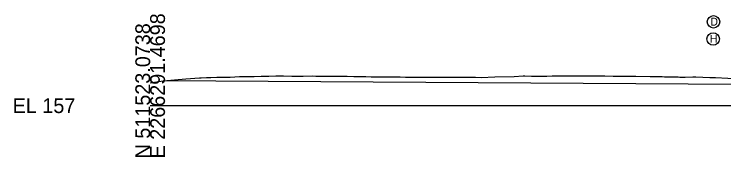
# Model space of a CAD drawing. Extents: x -516 to 303, y -10 to 5017.
# Drawn here: x -25.7 to 108.4, y 2990.3 to 3017.3 of the extents above; entities that cross this region are included whole.
import ezdxf

# ---------------------------------------------------------------- set-up
doc = ezdxf.new("R2010")
doc.units = 0
for name, color, linetype in [('Default', 7, 'Continuous'), ('Exist Cross Section Cell', 7, 'Continuous'), ('Exist XS Ground Line', 7, 'Continuous'), ('Prop Road Sect_ Material - Bubble + Leader + Bubble Tx', 7, 'Continuous'), ('Prop Road Sect_ Material - Contact (General - Major)', 7, 'Continuous'), ('Prop Road Sect_ Material - Tx (Composite Desc)', 7, 'Continuous')]:
    doc.layers.add(name, color=color, linetype=linetype)

msp = doc.modelspace()

# ---------------------------------------------------------------- linework, layer by layer
at = {"layer": 'Exist Cross Section Cell'}
msp.add_line((0, 3000), (150, 3000), dxfattribs=at)
at = {"layer": 'Exist XS Ground Line'}
msp.add_lwpolyline([(0, 3004.33), (2.46, 3004.71), (6.74, 3005.05), (9.34, 3005.26), (9.66, 3005.28), (10.63, 3005.32), (11.46, 3005.36), (12.58, 3005.37), (14.15, 3005.39), (14.45, 3005.4), (15.09, 3005.42), (16.89, 3005.49), (18.46, 3005.52), (19.65, 3005.54), (20.96, 3005.57), (21.94, 3005.58), (22.43, 3005.59), (23.77, 3005.62), (24.36, 3005.62), (25.18, 3005.62), (26.79, 3005.61), (27.56, 3005.61), (27.93, 3005.61), (28.94, 3005.61), (30.67, 3005.62), (31.31, 3005.61), (32.68, 3005.59), (33.43, 3005.58), (35.06, 3005.57), (36.19, 3005.56), (37.2, 3005.55), (38.51, 3005.53), (38.96, 3005.53), (40.73, 3005.49), (41.74, 3005.47), (44.49, 3005.46), (46.31, 3005.44), (47.26, 3005.43), (48.23, 3005.42), (50.17, 3005.41), (52.78, 3005.42), (55.19, 3005.41), (55.73, 3005.41), (56.05, 3005.41), (57.66, 3005.4), (58.36, 3005.39), (60.27, 3005.38), (61.1, 3005.37), (61.45, 3005.37), (62.53, 3005.36), (65.13, 3005.44), (68.76, 3005.53), (70.5, 3005.62), (70.82, 3005.62), (72.06, 3005.58), (73.8, 3005.6), (74.93, 3005.61), (75.98, 3005.62), (77.68, 3005.64), (78.3, 3005.64), (79.61, 3005.65), (80.45, 3005.65), (81.18, 3005.66), (83.19, 3005.66), (84.08, 3005.66), (84.77, 3005.66), (85.93, 3005.63), (87.51, 3005.6), (87.99, 3005.59), (88.31, 3005.59), (88.71, 3005.6), (89.44, 3005.6), (89.77, 3005.61), (91.45, 3005.57), (91.78, 3005.56), (94.45, 3005.5), (95.82, 3005.51), (96.76, 3005.49), (97.22, 3005.48), (97.76, 3005.47), (99.76, 3005.43), (100.11, 3005.42), (101.1, 3005.4), (102.54, 3005.46), (103.09, 3005.47), (105.73, 3005.34), (106.84, 3005.33), (111.46, 3005.08)], dxfattribs=at)
at = {"layer": 'Prop Road Sect_ Material - Bubble + Leader + Bubble Tx'}
for centre in [(106.46, 3015.88), (106.38, 3012.63)]:
    msp.add_circle(centre, 1.18, dxfattribs=at)
at = {"layer": 'Prop Road Sect_ Material - Contact (General - Major)'}
msp.add_line((178.9, 3003.52), (2.46, 3004.71), dxfattribs=at)

# ---------------------------------------------------------------- texts
at = {"layer": 'Default'}
msp.add_text('-', height=0.0001, dxfattribs=at).set_placement((0, 3000))
at = {"layer": 'Exist Cross Section Cell'}
for s, p in [('E 2266291.4698', (2.8, 2990)), ('N 511523.0738', (0, 2990))]:
    msp.add_text(s, height=2.8, rotation=90, dxfattribs=at).set_placement(p)
msp.add_text('EL 157', height=2.8, dxfattribs=at).set_placement((-26, 2998.6))
at = {"layer": 'Prop Road Sect_ Material - Tx (Composite Desc)'}
for s, p in [('D', (105.85, 3015.15)), ('H', (105.73, 3011.9))]:
    msp.add_text(s, height=1.5, dxfattribs=at).set_placement(p)

doc.saveas('drawing.dxf')
